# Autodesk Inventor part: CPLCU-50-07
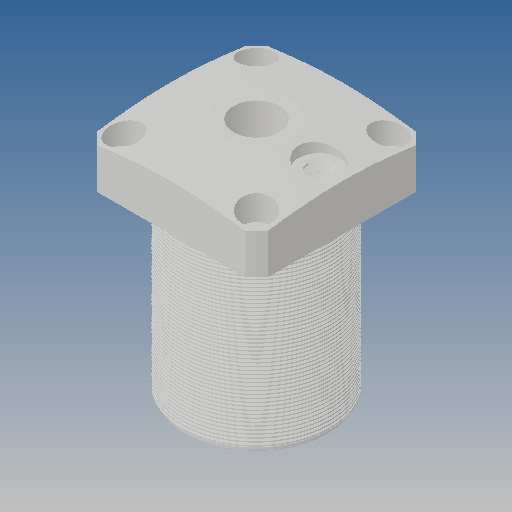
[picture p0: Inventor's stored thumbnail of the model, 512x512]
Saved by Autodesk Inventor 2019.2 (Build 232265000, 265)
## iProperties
Created: 2010-03
Part Number: CPLCU-50-07
Material: Ogólny
Document SubType Name: Modeling
Designer: CADENGINEERING4
Density: 1 g/cm^3
Appearance: Domyślna
Author: CADENGINEERING4
Revision Number: 3LAST_VERSION
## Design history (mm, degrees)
feature "Baza1"
node "Bryła1"
